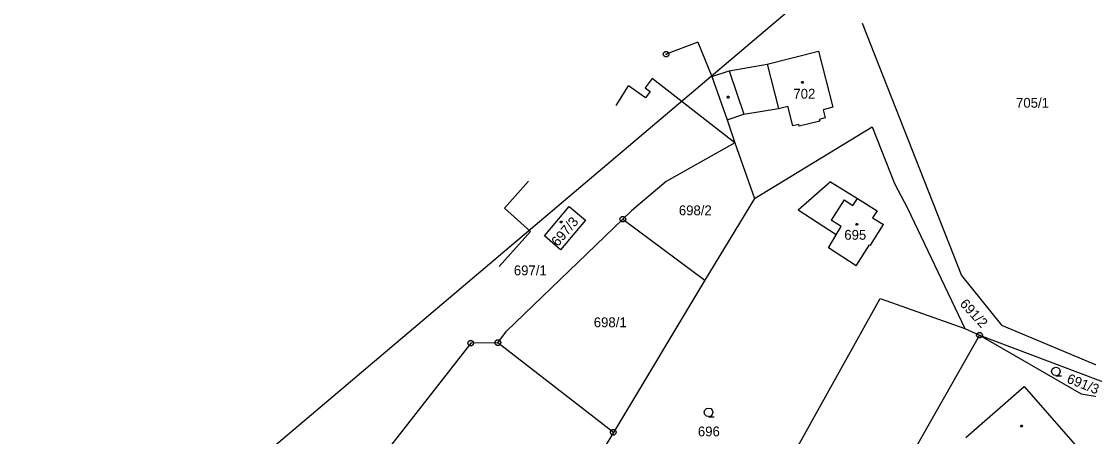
# Model space of a CAD drawing. Extents: x -759699 to -757730, y -1172308 to -1170857.
# Drawn here: x -758455.8 to -758271.3, y -1171136.3 to -1171064.4 of the extents above; entities that cross this region are included whole.
import ezdxf

# ---------------------------------------------------------------- set-up
doc = ezdxf.new("R2010")
doc.units = 0
for name, color, linetype in [('Vrstva 1', 7, 'Continuous'), ('Vrstva 11', 7, 'Continuous'), ('Vrstva 12', 7, 'Continuous'), ('Vrstva 2', 7, 'Continuous'), ('Vrstva 3', 7, 'Continuous'), ('Vrstva 4', 7, 'Continuous'), ('Vrstva 5', 7, 'Continuous'), ('Vrstva 8', 7, 'Continuous')]:
    doc.layers.add(name, color=color, linetype=linetype)

msp = doc.modelspace()

# ---------------------------------------------------------------- linework, layer by layer
at = {"layer": 'Vrstva 1'}
for p, q in [((-758310.43, -1171064.75), (-758310.43, -1171064.75)), ((-758310.43, -1171064.75), (-758293.28, -1171108.42)), ((-758338.88, -1171068.04), (-758344.34, -1171070.12)), ((-758338.88, -1171068.04), (-758338.88, -1171068.04)), ((-758338.88, -1171068.04), (-758336.41, -1171073.97)), ((-758326.89, -1171071.87), (-758318.02, -1171069.6)), ((-758318.02, -1171069.6), (-758315.53, -1171079.31)), ((-758344.34, -1171070.12), (-758344.34, -1171070.12)), ((-758333.44, -1171072.99), (-758326.89, -1171071.87)), ((-758336.41, -1171073.97), (-758333.44, -1171072.99)), ((-758346.75, -1171074.35), (-758346.75, -1171074.35)), ((-758332.46, -1171085.46), (-758346.75, -1171074.35)), ((-758336.41, -1171073.97), (-758333.81, -1171081.5)), ((-758324.91, -1171079.51), (-758323.28, -1171079.12)), ((-758322.45, -1171082.55), (-758323.28, -1171079.12)), ((-758333.81, -1171081.5), (-758330.9, -1171080.49)), ((-758330.9, -1171080.49), (-758324.91, -1171079.51)), ((-758315.53, -1171079.31), (-758317.18, -1171079.73)), ((-758317.18, -1171079.73), (-758316.82, -1171081.16)), ((-758333.81, -1171081.5), (-758332.46, -1171085.46)), ((-758329.08, -1171095.12), (-758308.72, -1171082.71)), ((-758321.42, -1171082.3), (-758322.45, -1171082.55)), ((-758321.35, -1171082.59), (-758321.42, -1171082.3)), ((-758317.79, -1171081.7), (-758321.35, -1171082.59)), ((-758316.82, -1171081.16), (-758317.86, -1171081.42)), ((-758317.86, -1171081.42), (-758317.79, -1171081.7)), ((-758308.72, -1171082.71), (-758308.72, -1171082.71)), ((-758308.72, -1171082.71), (-758308.72, -1171082.71)), ((-758308.72, -1171082.71), (-758304.83, -1171092.48)), ((-758332.46, -1171085.46), (-758344.34, -1171092.15)), ((-758332.46, -1171085.46), (-758329.08, -1171095.12)), ((-758368.14, -1171092.1), (-758372.29, -1171096.76)), ((-758368.14, -1171092.1), (-758368.14, -1171092.1)), ((-758344.34, -1171092.15), (-758350.3, -1171097.23)), ((-758315.92, -1171092.2), (-758321.5, -1171097.12)), ((-758315.92, -1171092.2), (-758311.25, -1171095.07)), ((-758304.83, -1171092.48), (-758302.62, -1171096.74)), ((-758329.08, -1171095.12), (-758337.62, -1171109.22)), ((-758311.25, -1171095.07), (-758307.83, -1171097.25)), ((-758372.29, -1171096.76), (-758367.78, -1171100.78)), ((-758365.38, -1171101.55), (-758361.08, -1171096.47)), ((-758361.08, -1171096.47), (-758358.26, -1171098.85)), ((-758350.3, -1171097.23), (-758351.82, -1171098.69)), ((-758314.96, -1171101.38), (-758321.5, -1171097.12)), ((-758307.83, -1171097.25), (-758308.63, -1171098.41)), ((-758302.62, -1171096.74), (-758292.69, -1171117.58)), ((-758351.82, -1171098.69), (-758371.91, -1171118.04)), ((-758358.26, -1171098.85), (-758362.58, -1171104)), ((-758351.82, -1171098.69), (-758337.62, -1171109.22)), ((-758351.82, -1171098.69), (-758351.82, -1171098.69)), ((-758309.03, -1171103.18), (-758306.77, -1171099.57)), ((-758308.63, -1171098.41), (-758306.77, -1171099.57)), ((-758367.78, -1171100.78), (-758373.21, -1171106.84)), ((-758316.29, -1171103.62), (-758314.96, -1171101.38)), ((-758362.58, -1171104), (-758365.38, -1171101.55)), ((-758311.47, -1171106.74), (-758309.18, -1171103.08)), ((-758309.18, -1171103.08), (-758309.03, -1171103.18)), ((-758311.47, -1171106.74), (-758316.29, -1171103.62)), ((-758373.21, -1171106.84), (-758373.21, -1171106.84)), ((-758293.28, -1171108.42), (-758286.34, -1171117.03)), ((-758337.62, -1171109.22), (-758353.46, -1171135.55)), ((-758346.54, -1171182.75), (-758307.35, -1171112.41)), ((-758307.35, -1171112.41), (-758292.69, -1171117.58)), ((-758292.69, -1171117.58), (-758290.15, -1171118.76)), ((-758286.34, -1171117.03), (-758256.83, -1171129.41)), ((-758373.42, -1171120.04), (-758371.91, -1171118.04)), ((-758371.91, -1171118.04), (-758371.91, -1171118.04)), ((-758290.15, -1171118.76), (-758304.99, -1171144.84)), ((-758290.15, -1171118.76), (-758272.6, -1171128.9)), ((-758290.15, -1171118.76), (-758263.67, -1171128.72)), ((-758378.11, -1171120.12), (-758397.72, -1171145.22)), ((-758373.42, -1171120.04), (-758378.11, -1171120.12)), ((-758378.11, -1171120.12), (-758378.11, -1171120.12)), ((-758353.46, -1171135.55), (-758373.42, -1171120.04)), ((-758373.42, -1171120.04), (-758373.42, -1171120.04)), ((-758292.53, -1171136.42), (-758282.43, -1171127.64)), ((-758282.43, -1171127.64), (-758273.63, -1171137.69)), ((-758272.6, -1171128.9), (-758264.59, -1171130.25)), ((-758353.46, -1171135.55), (-758370.31, -1171163.21))]:
    msp.add_line(p, q, dxfattribs=at)
at = {"layer": 'Vrstva 11'}
msp.add_line((-758128.76, -1170897.97), (-758510.97, -1171221.67), dxfattribs=at)
at = {"layer": 'Vrstva 12'}
for p, q in [((-758326.89, -1171071.87), (-758318.02, -1171069.6)), ((-758318.02, -1171069.6), (-758315.53, -1171079.31)), ((-758326.89, -1171071.87), (-758324.91, -1171079.51)), ((-758352.99, -1171079.02), (-758350.82, -1171075.61)), ((-758350.82, -1171075.61), (-758350.82, -1171075.61)), ((-758352.99, -1171079.02), (-758352.99, -1171079.02)), ((-758324.91, -1171079.51), (-758323.28, -1171079.12)), ((-758322.45, -1171082.55), (-758323.28, -1171079.12)), ((-758315.53, -1171079.31), (-758317.18, -1171079.73)), ((-758317.18, -1171079.73), (-758316.82, -1171081.16)), ((-758321.42, -1171082.3), (-758322.45, -1171082.55)), ((-758321.35, -1171082.59), (-758321.42, -1171082.3)), ((-758317.79, -1171081.7), (-758321.35, -1171082.59)), ((-758316.82, -1171081.16), (-758317.86, -1171081.42)), ((-758317.86, -1171081.42), (-758317.79, -1171081.7)), ((-758368.14, -1171092.1), (-758372.29, -1171096.76)), ((-758368.14, -1171092.1), (-758368.14, -1171092.1)), ((-758313.57, -1171095.34), (-758315.81, -1171098.87)), ((-758313.57, -1171095.34), (-758312.04, -1171096.31)), ((-758312.04, -1171096.31), (-758311.25, -1171095.07)), ((-758311.25, -1171095.07), (-758307.83, -1171097.25)), ((-758372.29, -1171096.76), (-758367.78, -1171100.78)), ((-758365.38, -1171101.55), (-758361.08, -1171096.47)), ((-758361.08, -1171096.47), (-758358.26, -1171098.85)), ((-758307.83, -1171097.25), (-758308.63, -1171098.41)), ((-758358.26, -1171098.85), (-758362.58, -1171104)), ((-758314.09, -1171099.91), (-758315.81, -1171098.87)), ((-758309.03, -1171103.18), (-758306.77, -1171099.57)), ((-758308.63, -1171098.41), (-758306.77, -1171099.57)), ((-758367.78, -1171100.78), (-758373.21, -1171106.84)), ((-758316.29, -1171103.62), (-758314.96, -1171101.38)), ((-758314.96, -1171101.38), (-758314.09, -1171099.91)), ((-758362.58, -1171104), (-758365.38, -1171101.55)), ((-758311.47, -1171106.74), (-758309.18, -1171103.08)), ((-758309.18, -1171103.08), (-758309.03, -1171103.18)), ((-758311.47, -1171106.74), (-758316.29, -1171103.62)), ((-758373.21, -1171106.84), (-758373.21, -1171106.84)), ((-758292.53, -1171136.42), (-758282.43, -1171127.64)), ((-758282.43, -1171127.64), (-758273.63, -1171137.69))]:
    msp.add_line(p, q, dxfattribs=at)
at = {"layer": 'Vrstva 3'}
for points in [[(-758276.94, -1171125.74), (-758277.32, -1171125.64), (-758277.59, -1171125.37), (-758277.69, -1171125), (-758277.59, -1171124.63), (-758277.32, -1171124.36), (-758276.95, -1171124.26), (-758276.58, -1171124.36), (-758276.31, -1171124.63), (-758276.21, -1171125.01), (-758276.31, -1171125.39), (-758276.58, -1171125.66), (-758276.96, -1171125.76), (-758275.96, -1171125.76)], [(-758336.99, -1171132.82), (-758337.37, -1171132.72), (-758337.64, -1171132.45), (-758337.74, -1171132.08), (-758337.64, -1171131.71), (-758337.37, -1171131.44), (-758337, -1171131.34), (-758336.63, -1171131.44), (-758336.36, -1171131.71), (-758336.26, -1171132.09), (-758336.36, -1171132.47), (-758336.63, -1171132.74), (-758337.01, -1171132.84), (-758336.01, -1171132.84)]]:
    msp.add_lwpolyline(points, dxfattribs=at)
at = {"layer": 'Vrstva 4'}
for p, q in [((-758326.89, -1171071.87), (-758324.91, -1171079.51)), ((-758333.44, -1171072.99), (-758330.9, -1171080.49)), ((-758346.75, -1171074.35), (-758347.95, -1171075.97)), ((-758352.99, -1171079.02), (-758350.82, -1171075.61)), ((-758347.89, -1171077.69), (-758350.82, -1171075.61)), ((-758350.82, -1171075.61), (-758350.82, -1171075.61)), ((-758347.95, -1171075.97), (-758347.09, -1171076.61)), ((-758347.09, -1171076.61), (-758347.89, -1171077.69)), ((-758352.99, -1171079.02), (-758352.99, -1171079.02)), ((-758313.57, -1171095.34), (-758315.81, -1171098.87)), ((-758313.57, -1171095.34), (-758312.04, -1171096.31)), ((-758312.04, -1171096.31), (-758311.25, -1171095.07)), ((-758314.09, -1171099.91), (-758315.81, -1171098.87)), ((-758314.96, -1171101.38), (-758314.09, -1171099.91))]:
    msp.add_line(p, q, dxfattribs=at)
at = {"layer": 'Vrstva 5'}
for points in [[(-758320.68, -1171074.84), (-758320.59, -1171074.99), (-758320.68, -1171075.14), (-758320.86, -1171075.14), (-758320.95, -1171074.99), (-758320.86, -1171074.84)], [(-758333.51, -1171077.42), (-758333.42, -1171077.57), (-758333.51, -1171077.72), (-758333.69, -1171077.72), (-758333.78, -1171077.57), (-758333.69, -1171077.42)], [(-758362.4, -1171099.02), (-758362.31, -1171099.17), (-758362.4, -1171099.32), (-758362.58, -1171099.32), (-758362.67, -1171099.17), (-758362.58, -1171099.02)], [(-758311.26, -1171099.39), (-758311.17, -1171099.54), (-758311.26, -1171099.69), (-758311.44, -1171099.69), (-758311.53, -1171099.54), (-758311.44, -1171099.39)], [(-758282.8, -1171134.29), (-758282.71, -1171134.44), (-758282.8, -1171134.59), (-758282.98, -1171134.59), (-758283.07, -1171134.44), (-758282.98, -1171134.29)]]:
    msp.add_lwpolyline(points, close=True, dxfattribs=at)
at = {"layer": 'Vrstva 8'}
for p, q in [((-758344.46, -1171070.12), (-758344.22, -1171070.12)), ((-758351.94, -1171098.69), (-758351.7, -1171098.69)), ((-758290.27, -1171118.76), (-758290.03, -1171118.76)), ((-758378.23, -1171120.12), (-758377.99, -1171120.12)), ((-758373.54, -1171120.04), (-758373.3, -1171120.04)), ((-758353.58, -1171135.55), (-758353.34, -1171135.55))]:
    msp.add_line(p, q, dxfattribs=at)
for points in [[(-758344.19, -1171069.64), (-758343.94, -1171069.82), (-758343.84, -1171070.11), (-758343.94, -1171070.4), (-758344.19, -1171070.58), (-758344.5, -1171070.58), (-758344.75, -1171070.4), (-758344.85, -1171070.11), (-758344.75, -1171069.82), (-758344.5, -1171069.64)], [(-758351.67, -1171098.21), (-758351.42, -1171098.39), (-758351.32, -1171098.68), (-758351.42, -1171098.97), (-758351.67, -1171099.15), (-758351.98, -1171099.15), (-758352.23, -1171098.97), (-758352.33, -1171098.68), (-758352.23, -1171098.39), (-758351.98, -1171098.21)], [(-758377.96, -1171119.64), (-758377.71, -1171119.82), (-758377.61, -1171120.11), (-758377.71, -1171120.4), (-758377.96, -1171120.58), (-758378.27, -1171120.58), (-758378.52, -1171120.4), (-758378.62, -1171120.11), (-758378.52, -1171119.82), (-758378.27, -1171119.64)], [(-758373.27, -1171119.56), (-758373.02, -1171119.74), (-758372.92, -1171120.03), (-758373.02, -1171120.32), (-758373.27, -1171120.5), (-758373.58, -1171120.5), (-758373.83, -1171120.32), (-758373.93, -1171120.03), (-758373.83, -1171119.74), (-758373.58, -1171119.56)], [(-758290, -1171118.28), (-758289.75, -1171118.46), (-758289.65, -1171118.75), (-758289.75, -1171119.04), (-758290, -1171119.22), (-758290.31, -1171119.22), (-758290.56, -1171119.04), (-758290.66, -1171118.75), (-758290.56, -1171118.46), (-758290.31, -1171118.28)], [(-758353.31, -1171135.07), (-758353.06, -1171135.25), (-758352.96, -1171135.54), (-758353.06, -1171135.83), (-758353.31, -1171136.01), (-758353.62, -1171136.01), (-758353.87, -1171135.83), (-758353.97, -1171135.54), (-758353.87, -1171135.25), (-758353.62, -1171135.07)]]:
    msp.add_lwpolyline(points, close=True, dxfattribs=at)

# ---------------------------------------------------------------- texts
at = {"layer": 'Vrstva 2'}
for s, p in [('702', (-758322.333, -1171077.82)), ('705/1', (-758283.839, -1171079.39)), ('698/2', (-758342.134, -1171097.99)), ('695', (-758313.531, -1171102.23)), ('697/1', (-758370.665, -1171108.38)), ('698/1', (-758356.842, -1171117.36)), ('696', (-758338.844, -1171136.24))]:
    msp.add_text(s, height=1.7, dxfattribs=at).set_placement(p)
for s, rotation, p in [('697/3', 49.50355, (-758363.064, -1171103.508)), ('691/2', 312.72036, (-758293.673, -1171113.419)), ('691/3', 338.56076, (-758275.193, -1171126.911))]:
    msp.add_text(s, height=1.7, rotation=rotation, dxfattribs=at).set_placement(p)

doc.saveas('drawing.dxf')
